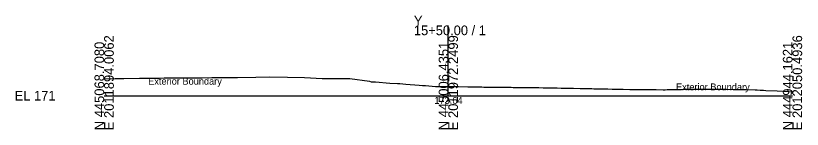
# Model space of a CAD drawing. Extents: x -26 to 3203, y -10 to 9532.
# Drawn here: x -25.7 to 202.8, y 9490.3 to 9523.1 of the extents above; entities that cross this region are included whole.
import ezdxf

# ---------------------------------------------------------------- set-up
doc = ezdxf.new("R2010")
doc.units = 0
for name, color, linetype in [('Default', 7, 'Continuous'), ('Exist Cross Section Cell', 7, 'Continuous'), ('Exist XS Center Line Elevation Label', 7, 'Continuous'), ('Exist XS Ground Line', 7, 'Continuous'), ('Scratch_Level_0', 7, 'Continuous')]:
    doc.layers.add(name, color=color, linetype=linetype)

msp = doc.modelspace()

# ---------------------------------------------------------------- linework, layer by layer
at = {"layer": 'Exist Cross Section Cell'}
for p, q in [((100, 9500), (100, 9520.3)), ((0, 9500), (100, 9500)), ((100, 9500), (200, 9500))]:
    msp.add_line(p, q, dxfattribs=at)
at = {"layer": 'Exist XS Ground Line'}
msp.add_lwpolyline([(0, 9504.84), (3.16, 9504.98), (5.74, 9505), (10.28, 9505.02), (15.98, 9505.11), (17.39, 9505.15), (18.52, 9505.14), (28.44, 9505.21), (31.3, 9505.22), (31.63, 9505.24), (32.04, 9505.23), (38.75, 9505.3), (44.09, 9505.39), (48.1, 9505.43), (53.29, 9505.35), (58.21, 9505.23), (63.31, 9504.99), (66.43, 9505.01), (71.34, 9504.93), (77.06, 9504.16), (77.6, 9503.99), (78.85, 9503.96), (82.99, 9503.66), (85.27, 9503.48), (85.88, 9503.54), (87.7, 9503.29), (91.5, 9503.05), (92.46, 9502.99), (93.39, 9502.91), (96.26, 9502.66), (97.25, 9502.65), (98.79, 9502.65), (99.86, 9502.64), (100.43, 9502.64), (102.23, 9502.61), (102.93, 9502.61), (105.66, 9502.56), (106.2, 9502.56), (107.93, 9502.54), (109.3, 9502.52), (109.72, 9502.52), (110.27, 9502.51), (111.51, 9502.5), (112.48, 9502.48), (113.29, 9502.47), (114.29, 9502.45), (115.68, 9502.43), (116.83, 9502.43), (118.28, 9502.42), (118.87, 9502.41), (120.4, 9502.38), (122.33, 9502.36), (125.27, 9502.33), (125.72, 9502.33), (126.3, 9502.32), (127.51, 9502.31), (128.46, 9502.29), (130.31, 9502.27), (131.65, 9502.24), (132.83, 9502.21), (134.85, 9502.17), (136.38, 9502.15), (138.31, 9502.11), (141.24, 9502.04), (141.71, 9502.03), (142.31, 9502.02), (144.44, 9501.98), (145.28, 9501.97), (146.33, 9501.95), (147.64, 9501.93), (148.84, 9501.92), (150.83, 9501.89), (152.7, 9501.83), (154.03, 9501.8), (154.35, 9501.79), (155.95, 9501.77), (157.21, 9501.77), (157.75, 9501.77), (158.41, 9501.77), (160.41, 9501.75), (162.42, 9501.73), (163.05, 9501.74), (163.58, 9501.75), (164.88, 9501.79), (166.37, 9501.82), (166.82, 9501.83), (168.32, 9501.86), (170.47, 9501.89), (171.98, 9501.91), (173.25, 9501.92), (173.79, 9501.92), (174.45, 9501.91), (176.4, 9501.9), (177.3, 9501.89), (178.43, 9501.87), (179.67, 9501.85), (180.81, 9501.84), (182.82, 9501.83), (184.45, 9501.8), (186.02, 9501.77), (186.53, 9501.76), (189.18, 9501.69), (189.77, 9501.67), (190.6, 9501.63), (191.6, 9501.57), (192.29, 9501.54), (195.56, 9501.37), (198.76, 9501.18), (199.6, 9501.12), (200, 9501.09)], dxfattribs=at)

# ---------------------------------------------------------------- texts
at = {"layer": 'Default'}
msp.add_text('-', height=0.0001, dxfattribs=at).set_placement((0, 9500))
at = {"layer": 'Exist Cross Section Cell'}
for s, p in [('Y', (90, 9520.3)), ('15+50.00 / 1', (90, 9517.5)), ('EL 171', (-26, 9498.6))]:
    msp.add_text(s, height=2.8, dxfattribs=at).set_placement(p)
for s, p in [('E 2011894.0062', (2.8, 9490)), ('E 2011972.2499', (102.8, 9490)), ('E 2012050.4936', (202.8, 9490)), ('N 445068.7080', (0, 9490)), ('N 445006.4351', (100, 9490)), ('N 444944.1621', (200, 9490))]:
    msp.add_text(s, height=2.8, rotation=90, dxfattribs=at).set_placement(p)
at = {"layer": 'Exist XS Center Line Elevation Label'}
msp.add_text('173.64', height=2, dxfattribs=at).set_placement((95.96, 9497.64))
at = {"layer": 'Scratch_Level_0'}
for p in [(12.79, 9503.19), (166.16, 9501.53)]:
    msp.add_text('Exterior Boundary', height=2, dxfattribs=at).set_placement(p)

doc.saveas('drawing.dxf')
